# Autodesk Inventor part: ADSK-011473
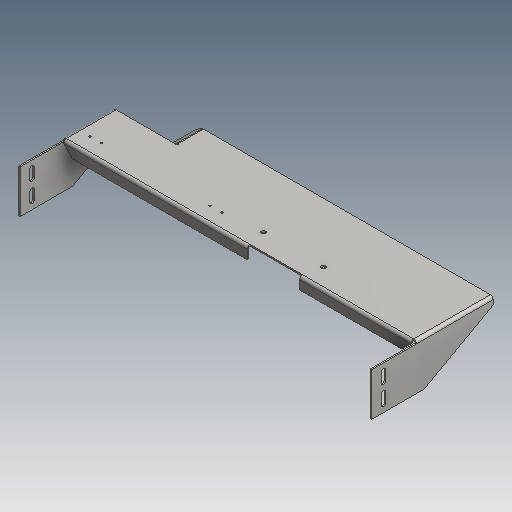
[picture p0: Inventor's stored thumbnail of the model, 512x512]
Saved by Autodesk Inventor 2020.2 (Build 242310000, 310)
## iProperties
Created: 2000-02
Part Number: ADSK-011473
Document SubType Name: Tôlerie
Description: FSHTPH,SS,CP,01,101,040,293,090,PAN,TRANSFER
Designer: gpurviance
Material: 1.0312 DC05
Density: 1 g/cm^3
Sheet Metal Rule: Stahlblech 1.0312 - DC05 -   3.0 mm
Appearance: Stahl
Mass: 487.517 g
Surface Area: 3339.23 cm^2
Volume: 487.517 cm^3
Flat Pattern Width: 25.69 cm
Flat Pattern Length: 92.9572 cm
Flat Pattern Area: 2388.07 cm^2
Sheet Metal Width: 256,900 mm
Sheet Metal Length: 929,572 mm
Sheet Metal Area: 238806,965 mm^2
Control State: 0
Checked Out: False
Master: False
Shininess: 57.0
Length Units: 11269
Angle Units: 11279
Time Units: 11290
Mass Units: 11283
Length Display Precision: 3
Angle Display Precision: 2
Compacted: True
Cutlength: 10.13 X 36.66 (372 SI)
Material Desc: SHEET,S/S,0.188
Material_Number: A101293
G_L: 256,9x929,6 mm
Thickness: 3,000 mm
Dimensions: 97x256,9x746 mm
Mass: 0,488 kg
Semi finished: Stahlblech 1.0312 - DC05 -   3.0 mm
DocNumber: ADSK-011473.ipt
Folder: 01 - Themengebiete\Simplification\01 - Packaging machine\
VDS_Category: 3D Komponenten
VLT_Material: 1.0312 DC05
Density: 8.03
Volumn: 779.9198039401276
Area: 3420.4340657456337
PropertySet Name: Model Information
Author: gpurviance
Revision Number: -
Title: FSHTPH,SS,CP,01,101,040,293,090,PAN,TRANSFER
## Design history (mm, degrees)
derived "ADSK-011472.ipt"
workplane "Arbeitsebene1"
node "Solide1"
node "Corps solides"
node "Corps surfaciques"
node "FonctionRepérage2"
node "FlatPattern"
feature "Volumenkörper1::ADSK-011472.ipt" dims "d0" = 10
feature "Extrusion_mise_à_plat2" dims "d0" = 3 (derived)
other parameters: "Thickness" = 3 (derived), "BendRadius" = 3 (= Thickness), "BendReliefWidth" = 3 (= Thickness), "BendReliefDepth" = 1.5 (= 0.5 x Thickness), "CornerReliefSize" = 12 (= 4 x Thickness), "SeamGap" = 0.00508, "MinimumRemnant" = 6 (= 2 x Thickness), "TransitionRadius" = 3 (= BendRadius), "TailleRayonJacobi" = 3 (= BendRadius), "TailleJeu" = 3 (= Thickness)
